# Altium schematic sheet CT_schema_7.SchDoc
size 278 x 170 mm
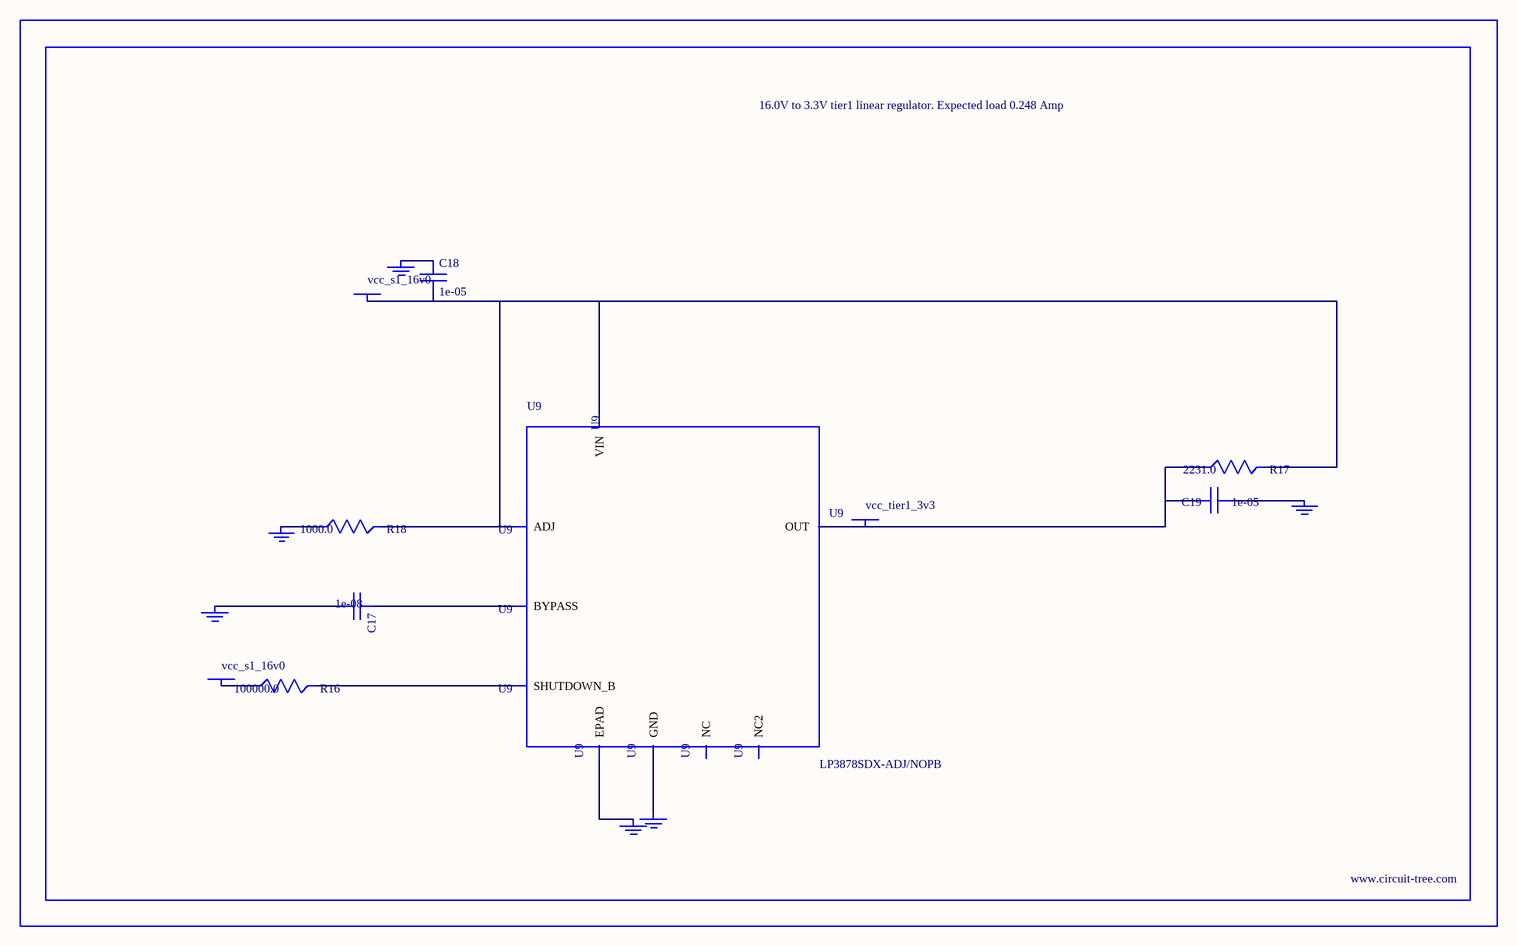
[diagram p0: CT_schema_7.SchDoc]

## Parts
BORDER6  (no value)
C17  1e-08  [C0402]
C18  1e-05  [C1210]
C19  1e-05  [C1210]
GND_INSTANCE_6_0  (no value)
GND_INSTANCE_6_1  (no value)
GND_INSTANCE_6_2  (no value)
GND_INSTANCE_6_3  (no value)
GND_INSTANCE_6_4  (no value)
GND_INSTANCE_6_5  (no value)
POWER_INSTANCE_6_0  vcc_s1_16v0
POWER_INSTANCE_6_1  vcc_s1_16v0
POWER_INSTANCE_6_2  vcc_tier1_3v3
R16  100000.0  [R0603]
R17  2231.0  [R0603]
R18  1000.0  [R0603]
U9  LP3878SDX-ADJ/NOPB  [WSON-8]

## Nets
NetC17_1: C17.1 U9.1(BYPASS)
NetC17_2: C17.2 GND_INSTANCE_6_0.0(GND)
NetC18_1: C18.1 GND_INSTANCE_6_1.0(GND)
NetC18_2: C18.2 POWER_INSTANCE_6_0.0(PWR) R17.2 R18.2 U9.4(VIN) U9.6(ADJ)
NetC19_1: C19.1 GND_INSTANCE_6_2.0(GND)
NetC19_2: C19.2 POWER_INSTANCE_6_2.0(PWR) R17.1 U9.5(OUT)
NetGND_INSTANCE_6_3_0: GND_INSTANCE_6_3.0(GND) R18.1
NetGND_INSTANCE_6_4_0: GND_INSTANCE_6_4.0(GND) U9.PAD(EPAD)
NetGND_INSTANCE_6_5_0: GND_INSTANCE_6_5.0(GND) U9.3(GND)
NetPOWER_INSTANCE_6_1_0: POWER_INSTANCE_6_1.0(PWR) R16.1
NetR16_2: R16.2 U9.8(SHUTDOWN_B)

Not connected (* = marked no-connect by the designer): U9 2(NC) 7(NC2)

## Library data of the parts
BORDER6 = BORDER_PAGE6
C17 = C0402C103K3RAC
C18 = C1210C106K5PACTU
C19 = GRM32DR61E106MA12L
GND_INSTANCE_6_0-GND_INSTANCE_6_5 = GND
POWER_INSTANCE_6_0-POWER_INSTANCE_6_2 = PWR
R16 = RC0603JR-07100KL
R17 = R17
R18 = RC0603JR-071KL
